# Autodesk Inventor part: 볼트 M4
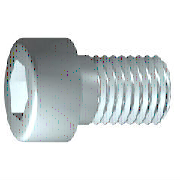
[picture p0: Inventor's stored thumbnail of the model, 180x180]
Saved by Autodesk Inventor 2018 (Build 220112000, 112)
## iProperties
IsCustomPart: 1
Created: 2012-02
Part Number: 볼트 M4
Material: 강철, 연강
Description: 6각머리 태핑 나사
Document SubType Name: Modeling
Standard: KS B 1003
Designer: mduedu
Standards Organization: KS
Language: ko-KR
Size Designation: M 4 x 10
Categories: <MemberInstance><Categories><Category DisplayName="조임쇠" InternalName="e4da775c-781d-43d5-af7c-5136215cf5a6" Mnemonic="FSTN"><Category DisplayName="볼트" InternalN
Density: 7.86 g/cm^3
Appearance: 강철
Mass: 2.0371 g
Surface Area: 3.0572 cm^2
Volume: 0.259174 cm^3
Author: mduedu
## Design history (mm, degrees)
sketch "스케치1"
  geometry: L1 (-1, 0)-(10, 0); L2 (10, 0)-(10, 2); L3 (10, 2)-(1.75, 2); L4 (1.75, 2)-(1.32, 2); L5 (1.32, 2)-(0, 2); L6 (0, 2)-(0, 3.5); L7 (0, 3.5)-(-4, 3.5); L8 (-4, 3.5)-(-4, 1.732); L9 (-4, 1.732)-(-2, 1.732); L10 (-2, 1.732)-(-1, 0); L11 (-6.8, 0)-(12.8, 0) reference; L12 (0, -0.7)-(0, 4.2) reference; L13 (1.75, 2)-(0, 2)
  constraints: 22 end point, 6 parallel, 2 collinear, 2 perpendicular, 1 horizontal, 1 point on line
  dimensions: "d1" = 8.25 distance from line of L3.end L2 (= GEL); "d2" = 0.42952 distance of L4.end L3.end (computed from GAL); "d3" = 4 distance between parallel lines of L8 L6 (= KOH); "d4" = 2 distance of L8.end L9.end (= INTI); "d5" = 60 deg angle of L10 L1; "d6" = 4 diameter of L3 L1 (= GD); "d7" = 4 diameter of L5 L1 (= BDM); "d8" = 3.4641 diameter of L9 L1 (= 1.1547 x SW); "d9" = 7 diameter of L7 L1 (= KOD); "d26" = 10 distance between parallel lines of L12 L2 (= NLG)
revolve "본체" sketch "스케치1" stored, may be unused: angle "d10" = 90 deg
sketch "스케치2"
  geometry: L1 (0, -4.9)-(0, 4.9) reference; L2 (-4.9, 0)-(4.9, 0) reference; L3 (1.732, 0)-(0.866, -1.5); L4 (0.866, -1.5)-(-0.866, -1.5); L5 (-0.866, -1.5)-(-1.732, 0); L6 (-1.732, 0)-(-0.866, 1.5); L7 (-0.866, 1.5)-(0.866, 1.5); L8 (0.866, 1.5)-(1.732, 0); 2 further points
  constraints: 12 end point, 1 coincident, 1 horizontal alignment, 1 point on line, 12 other
extrude "슬롯" join sketch "스케치2" stored distance "d11" = 10; taper "d12" = 0 deg
workplane "Work Plane1"
fillet "Fillet2" dims "d30" = 0.1 (= R)
body "Solid1"
fillet "모깎기1" dims "d17" = 0.4 (= RR)
feature "스레드" dims "d13" = 8.25 (= GEL), "d14" = 0
chamfer "모따기1" distance "d15" = 0.42941 (= -0.5 x SPD + 0.5 x GD); stored, may be unused: second distance "d16" = 0.42941 (= GUL), angle "d27" = 45 deg
other parameters: "GD" = 4 (= NND) [user parameter; used in 2 equation terms], "NLG" = 10 [user parameter; used in 1 equation term], "GEL" = 8.25 [user parameter; used in 2 equation terms], "KOD" = 7 [user parameter; used in 1 equation term], "KOH" = 4 [user parameter; used in 1 equation term], "INTI" = 2 [user parameter; used in 1 equation term], "GAL" = 0.42941 (= 0.61345 x PTC) [user parameter; used in 1 equation term], "GUL" = 0.42941 (= 0.61345 x PTC) [user parameter; used in 1 equation term], "BDM" = 4 (= NND) [user parameter; used in 1 equation term], "SW" = 3 [user parameter; used in 2 equation terms], "RR" = 0.4 [user parameter; used in 1 equation term], "SPD" = 3.14117 (= NND - 1.2269 x PTC) [user parameter; used in 1 equation term], "d19" = 0, "d28" = 0, "d29" = 0, "R" = 0.1 [user parameter; used in 1 equation term], "PHH" = 0.2 [user parameter], "GD1" = 3.14117 (= THREADDIA - 1.2269 x PTC) [user parameter], "THREADDIA" = 4 [user parameter; used in 1 equation term], "FAWI" = 45 deg [user parameter], "TPU" = 14.28571 (computed from PTC) [user parameter], "PTC" = 0.7 [user parameter; used in 5 equation terms], "NND" = 4 [user parameter; used in 3 equation terms], "TOA" = 30 deg [user parameter], "E0" = 3.465 (= 1.155 x SW) [user parameter]
